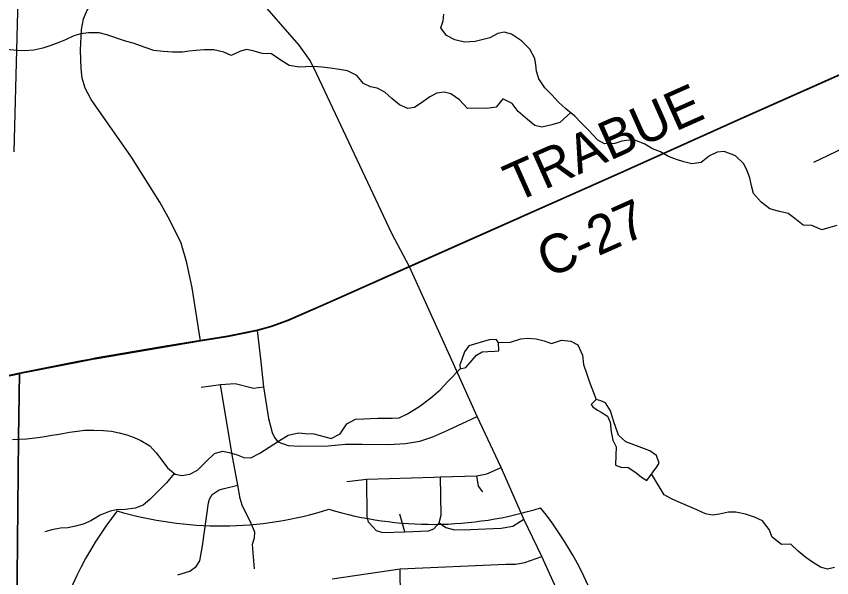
# Model space of a CAD drawing. Extents: x 114604 to 551442, y 316898 to 567001.
# Drawn here: x 172907 to 179238, y 393732 to 398094 of the extents above; entities that cross this region are included whole.
import ezdxf

# ---------------------------------------------------------------- set-up
doc = ezdxf.new("R2010")
doc.units = 0
for name, color, linetype in [('GE_P_Alignment', 7, 'Continuous'), ('GE_P_Alignment_1000_Cardinal_Points', 7, 'Continuous'), ('GE_P_Alignment_100_Cardinal_Points', 7, 'Continuous'), ('GE_P_Alignment_500_Bearings', 7, 'Continuous'), ('GE_P_Alignment_500_Distances', 7, 'Continuous'), ('GE_P_Alignment_500_Stations', 7, 'Continuous'), ('MT_X_Edge_Line', 7, 'Continuous'), ('PM_P_Cells', 7, 'Continuous'), ('PM_P_CL_Double_Solid', 7, 'Continuous')]:
    doc.layers.add(name, color=color, linetype=linetype)

msp = doc.modelspace()

# ---------------------------------------------------------------- linework, layer by layer
at = {"layer": 'GE_P_Alignment'}
for centre, start, end in [((176136.7, 396958.8), 253.42184, 287.40369), ((174784.2, 392514.6), 14.60614, 38.74383), ((175909.3, 392522.7), 142.08169, 166.21938), ((174492.9, 396947), 253.42183, 287.40368)]:
    msp.add_arc(centre, 2812.7, start, end, dxfattribs=at)
at = {"layer": 'GE_P_Alignment_1000_Cardinal_Points'}
for p, q in [((179098.5, 396961.4), (179422.3, 397115.9)), ((174778.3, 395651.7), (174802.6, 395433.5))]:
    msp.add_line(p, q, dxfattribs=at)
for points in [[(174802.6, 395433.5), (174826.9, 395215.2), (174866.3, 394969), (174892.7, 394860.7), (174910.9, 394820.7), (174939, 394788.6), (175019.3, 394758.8), (175109.5, 394753.1), (175329.9, 394755.9), (175464.2, 394770.4), (175592.5, 394768.8), (175796.9, 394767.5), (175929.1, 394773.9), (176039.3, 394792.3), (176141.4, 394826.8), (176257.5, 394877.4), (176486.7, 394985.3)], [(174342.3, 395212), (174491.8, 395233.9), (174606.8, 395241), (174749.2, 395205.3), (174826.9, 395215.2)], [(174757.9, 393800.9), (174743.4, 393955.4), (174741.2, 393991.5), (174757.1, 394041.7), (174759, 394085.8), (174730.7, 394152), (174660.1, 394294.1), (174645.9, 394346.3), (174627, 394451.5), (174584.6, 394687.1), (174491.8, 395233.9)], [(174160.8, 393752.8), (174254.9, 393781.2), (174302.9, 393817.5), (174332.8, 393863.7), (174352.5, 393978.1), (174399.5, 394313.3), (174407.4, 394341.5), (174427.3, 394377.6), (174483.3, 394413.9), (174521.4, 394424.1), (174627, 394451.5)]]:
    msp.add_lwpolyline(points, dxfattribs=at)
at = {"layer": 'GE_P_Alignment_100_Cardinal_Points'}
for p, q in [((175925.2, 394088.8), (175885.2, 394226.1)), ((175895.6, 393164.3), (175888.9, 393800.3))]:
    msp.add_line(p, q, dxfattribs=at)
for points in [[(174338.3, 395571.3), (174272, 395983.1), (174231.9, 396178.6), (174187.1, 396331.8), (174099.4, 396509.8), (174022.8, 396650), (173801.4, 396998.5), (173488.5, 397448.8), (173440.9, 397536), (173419, 397612.7), (173409.9, 397689.5), (173404.6, 397830.3), (173414.2, 397992.6), (173428.5, 398073.9), (173457.9, 398142.4), (173504.5, 398198.3), (173457, 398264.1), (173426.8, 398315.1), (173417.8, 398374.8), (173441.4, 398951.4), (173444.9, 399203.4), (173453.8, 399399.2)], [(176149.6, 394513.9), (176201.8, 394515.7), (176483.6, 394522), (176560.3, 394539.6), (176671, 394587.4)], [(175474, 394480.4), (175627.7, 394496.6), (176149.6, 394513.9)], [(175677.3, 394123.3), (175642.8, 394163.7), (175630.8, 394208.2), (175627.7, 394496.6)], [(176191.6, 394156.9), (176206.1, 394216.8), (176201.8, 394515.7)], [(176529.3, 394398.5), (176497, 394443.1), (176483.6, 394522)], [(175677.3, 394123.3), (175701, 394097.9), (175750.2, 394083.3), (175925.2, 394088.8), (176106.6, 394096.5), (176149.2, 394111.8), (176191.6, 394156.9)], [(176191.6, 394156.9), (176243.1, 394121), (176309.4, 394104.4), (176433.2, 394107.4), (176672.3, 394115.6), (176761.8, 394133.3), (176848.9, 394187.3)], [(175358.7, 393721.9), (175888.9, 393800.3), (176708.4, 393836.1), (176783.2, 393836.7), (176855.6, 393850), (176987.7, 393895.8)]]:
    msp.add_lwpolyline(points, dxfattribs=at)
at = {"layer": 'GE_P_Alignment_500_Bearings'}
for points in [[(175959.8, 396147.2), (175824.2, 396407.3), (175242, 397645), (175190, 397751.4), (175103.8, 397870.3), (174856.2, 398154.6)], [(176826.9, 396532.7), (177573.6, 396864.7), (178528.5, 397294.1), (180048.7, 397969.9), (180095.3, 397990.2)], [(173499.7, 395429.9), (173520.8, 395433.5), (174034.9, 395521.7), (174338.3, 395571.3), (174548.9, 395606.3), (174778.3, 395651.7), (174888.9, 395683.5), (175017.9, 395729.1), (175314.2, 395860), (175959.8, 396147.2), (176826.9, 396532.7)], [(177624.3, 392506.8), (177277.8, 393256.9), (176987.7, 393895.8), (176848.9, 394187.3), (176671, 394587.4), (176486.7, 394985.3), (176302.2, 395393.9), (175959.8, 396147.2)], [(172927.2, 395316.3), (172932.4, 395317.4), (173386, 395407.6), (173489.2, 395428.1), (173499.7, 395429.9)], [(171624.5, 395056), (172075.6, 395138.4), (172765.6, 395281.9), (172828.6, 395295), (172927.2, 395316.3)]]:
    msp.add_lwpolyline(points, dxfattribs=at)
at = {"layer": 'GE_P_Alignment_500_Distances'}
for points in [[(180047.5, 397972.7), (178527.3, 397296.9), (177572.4, 396867.6), (175958.6, 396150), (175313, 395862.8), (175016.7, 395731.9), (174887.7, 395686.3), (174777.1, 395654.5), (174547.7, 395609.1), (174337.1, 395574.1), (174033.8, 395524.5), (173519.6, 395436.3), (173488, 395430.9), (173384.8, 395410.4), (172931.2, 395320.3), (172827.4, 395297.8)], [(172911.5, 393468.2), (172925.8, 394815.7), (172931.2, 395320.3), (173384.8, 395410.4), (173488, 395430.9), (173519.6, 395436.3), (174033.8, 395524.5), (174337.1, 395574.1), (174547.7, 395609.1), (174777.1, 395654.5), (174887.7, 395686.3), (175016.7, 395731.9), (175313, 395862.8), (175958.6, 396150), (177572.4, 396867.6), (178527.3, 397296.9), (180047.5, 397972.7)], [(165627.9, 393736.1), (166831.6, 393994.7), (167215.5, 394091.7), (167290.7, 394106.3), (167481.3, 394142.8), (167797.2, 394212.1), (168930.6, 394456.4), (169558.4, 394598.6), (171032.3, 394928.5), (171623.4, 395058.8), (172074.4, 395141.2), (172764.4, 395284.7), (172827.4, 395297.8), (172931.2, 395320.3), (172925.8, 394815.7), (172911.5, 393468.2)]]:
    msp.add_lwpolyline(points, dxfattribs=at)
at = {"layer": 'GE_P_Alignment_500_Stations'}
msp.add_lwpolyline([(172889.7, 397041.2), (172984.7, 400606.9), (173002.8, 401182), (172993.8, 401567.1), (172993.5, 401577.5)], dxfattribs=at)
at = {"layer": 'MT_X_Edge_Line'}
for points in [[(176651.7, 395558.1), (176631.9, 395582.3), (176577.8, 395580.6), (176533.7, 395566.9), (176463.6, 395547.3), (176421.5, 395533.5), (176387.1, 395487.6), (176366.8, 395427.6), (176350.5, 395385.6), (176354.3, 395353.5), (176396.4, 395365.3), (176446.8, 395423.1), (176481, 395461), (176525.2, 395486.8), (176569.2, 395488.5), (176623.3, 395492.1), (176653.3, 395494)], [(176653.3, 395494), (176651.7, 395558.1)], [(177371, 395078.5), (177384.9, 395058.4), (177420.8, 395034.1), (177448.7, 395017.9), (177496.5, 394987.5), (177518.2, 394941.3), (177525.7, 394865.1), (177539.3, 394800.9), (177565, 394748.6), (177562.6, 394680.5), (177560.1, 394606.3), (177610, 394588), (177656.1, 394589.7), (177719.8, 394547.2), (177761.6, 394512.8), (177803.5, 394486.5), (177880.2, 394594.3), (177898.4, 394622.2), (177876.7, 394680.5), (177827, 394716.9), (177743.1, 394749.5), (177639.3, 394786.2), (177583.6, 394838.7), (177544.3, 394951.2), (177520.8, 395027.5), (177481.2, 395089.9), (177445.2, 395106.1), (177409.3, 395116.4)], [(177409.3, 395116.4), (177371, 395078.5)]]:
    msp.add_lwpolyline(points, dxfattribs=at)
at = {"layer": 'PM_P_Cells'}
for points in [[(176941.6, 397717), (176933.9, 397767.2), (176894.3, 397837.6), (176828.7, 397904.1), (176753, 397954.7), (176695.1, 397971.1), (176645, 397959.4), (176582.8, 397927.7), (176522.6, 397910.1), (176470.5, 397898.4), (176388.4, 397892.9), (176312.5, 397911.4), (176246.7, 397945.9), (176203.1, 398004.3), (176221.4, 398058.3), (176225.7, 398110.4)], [(177210.3, 397344.9), (177126.8, 397268.9), (177064.7, 397251.2), (176986.5, 397233.7), (176932.6, 397246), (176876.9, 397292.5), (176805.2, 397355.1), (176757.6, 397415.5), (176685.8, 397454.1), (176633.4, 397388.2), (176561.3, 397378.7), (176491.2, 397379.1), (176411.2, 397377.6), (176349.6, 397446.1), (176281.8, 397490.7), (176229.9, 397505), (176171.8, 397497.4), (176117.6, 397467.7), (176063.3, 397429.9), (175999, 397386.2), (175946.9, 397378.5), (175883.1, 397407), (175823.4, 397455.5), (175767.7, 397505.9), (175709.8, 397536.4), (175657.9, 397546.7), (175602, 397573.1), (175552.4, 397633.6), (175478.6, 397670.1), (175416.6, 397680.5), (175346.6, 397691), (175278.7, 397699.5), (175212.7, 397703.9), (175154.6, 397702.2), (175104.6, 397698.5), (175026.6, 397711.1), (174948.9, 397761.7), (174889.1, 397802.1), (174817.1, 397804.6), (174755.2, 397823), (174697.2, 397835.4), (174647.1, 397823.7), (174576.9, 397790.1), (174519, 397814.5), (174441.1, 397833), (174367.1, 397833.5), (174305, 397827.9), (174248.9, 397822.2), (174198.9, 397816.5), (174120.8, 397815), (174048.8, 397819.5), (173974.8, 397827.9), (173906.9, 397852.4), (173815.1, 397885.1), (173755.2, 397901.5), (173611.4, 397950.5), (173551.5, 397964.9), (173467.5, 397965.4), (173409.4, 397957.8), (173355.2, 397942.1), (173289, 397912.4), (173238.9, 397890.7), (173174.7, 397867.1), (173114.5, 397847.4), (173042.4, 397829.8), (172968.3, 397826.3), (172910.3, 397828.6), (172830.3, 397837.2)], [(179278.8, 396469.6), (179224.7, 396453.9), (179160.6, 396434.2), (179084.7, 396468.8), (179016.7, 396471.2), (178951, 396523.7), (178899.2, 396562.2), (178833.3, 396576.6), (178757.4, 396597.1), (178689.7, 396649.7), (178630.1, 396716.2), (178616.4, 396776.4), (178602.8, 396838.6), (178581.2, 396892.9), (178555.5, 396947.2), (178491.9, 397009.7), (178402, 397044.4), (178350, 397038.7), (178289.8, 397009), (178225.4, 396959.3), (178153.3, 396947.7), (178091.4, 396962.1), (178033.5, 396982.5), (177971.6, 397005), (177907.8, 397041.5), (177847.9, 397063.9), (177786.1, 397100.3), (177716.2, 397128.9), (177664.2, 397131.2), (177608.2, 397123.5), (177554, 397105.8), (177474, 397104.3), (177422.1, 397132.7), (177350.6, 397209.3), (177290.9, 397267.8), (177243.2, 397318.2), (177173.5, 397374.8), (177117.8, 397427.3), (177066.2, 397483.7), (177010.5, 397538.2), (176964.9, 397608.6), (176947.3, 397666.9), (176941.6, 397717)], [(176651.7, 395558.1), (176743.8, 395561.5), (176824, 395587.1), (176874.1, 395592.8), (176944.1, 395588.3), (177006, 395571.9), (177063.9, 395551.5), (177140.1, 395577.1), (177212.1, 395570.6), (177267.9, 395540.2), (177303.4, 395459.8), (177311, 395387.6), (177336.5, 395313.3), (177354.2, 395259), (177409.3, 395116.4)], [(172879.1, 394806.2), (172931.1, 394807.9), (172987.2, 394811.6), (173053.2, 394819.2), (173113.3, 394826.8), (173183.4, 394838.4), (173241.5, 394848), (173321.6, 394863.6), (173381.7, 394871.2), (173435.8, 394876.9), (173509.8, 394878.4), (173583.9, 394875.9), (173645.8, 394869.5), (173705.8, 394857.1), (173765.7, 394842.7), (173823.6, 394820.3), (173875.5, 394797.9), (173945.3, 394755.4), (173992.9, 394703), (174038.6, 394644.6), (174080.2, 394584.2), (174140, 394535.7), (174191.9, 394525.3), (174256, 394535), (174314.2, 394566.7), (174378.7, 394632.4), (174447.1, 394696.1), (174507.3, 394715.8), (174561.3, 394705.4), (174621.2, 394687), (174675.1, 394666.6), (174727.1, 394664.3), (174799.3, 394699.9), (174869.7, 394745.6), (174942, 394793.2), (175018.3, 394838.8), (175098.5, 394858.4), (175150.5, 394852), (175216.5, 394849.6), (175296.4, 394829.1), (175352.3, 394812.7), (175422.6, 394850.3), (175473.1, 394926.2), (175541.4, 394963.8), (175605.4, 394965.4), (175657.5, 394969.1), (175713.5, 394970.7), (175771.6, 394972.4), (175825.6, 394972), (175879.6, 394973.7), (175945.9, 395005.4), (176040.3, 395064.9), (176124.7, 395128.5), (176199.2, 395192.2), (176257.6, 395255.9), (176354.2, 395354)], [(174134.2, 394540.4), (174073.5, 394470), (173997, 394390.3), (173944.6, 394338.5), (173892.3, 394294.7), (173830.1, 394271.1), (173754, 394261.5), (173686, 394260), (173635.9, 394248.2), (173559.6, 394216.7), (173487.3, 394173), (173427.1, 394147.3), (173367, 394131.7), (173306.9, 394120), (173250.9, 394116.4), (173182.7, 394102.8), (173128.6, 394087.1)], [(179259.9, 393809.8), (179205.8, 393798.2), (179151.9, 393812.5), (179090.1, 393853), (179038.3, 393887.4), (178978.6, 393937.9), (178920.9, 393992.4), (178848.9, 393990.8), (178775.2, 394045.4), (178751.5, 394105.7), (178699.9, 394174.2), (178638.1, 394202.6), (178568.2, 394225.1), (178494.3, 394241.6), (178438.2, 394242), (178368.1, 394226.4), (178314, 394218.7), (178258.1, 394229.1), (178190.2, 394259.6), (178064.5, 394314.5), (177998.7, 394343), (177936.8, 394375.4), (177840, 394537.8)]]:
    msp.add_lwpolyline(points, dxfattribs=at)

# ---------------------------------------------------------------- texts
at = {"layer": 'PM_P_CL_Double_Solid'}
for s, rotation, p in [('TRABUE', 23.97305, (176781.5, 396644.1)), ('C-27', 24.06227, (177037.7, 396055.8))]:
    msp.add_text(s, height=300.01, rotation=rotation, dxfattribs=at).set_placement(p)

doc.saveas('drawing.dxf')
